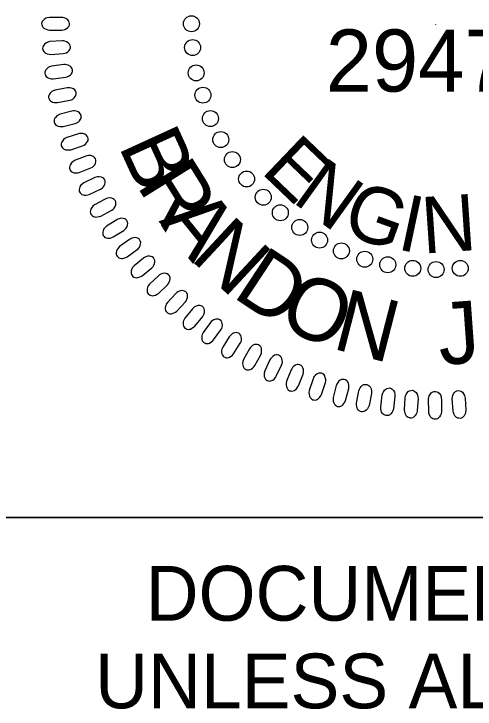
# Model space of a CAD drawing. Extents: x 505602 to 507286, y 483109 to 484209.
# Drawn here: x 507076.9 to 507123.2, y 484026.9 to 484096.7 of the extents above; entities that cross this region are included whole.
import ezdxf

# ---------------------------------------------------------------- set-up
doc = ezdxf.new("R2010")
doc.units = 0
for name, color, linetype in [('Sheet PE Seal Cell', 7, 'Continuous'), ('Sheet Profile CELL', 7, 'Continuous'), ('Sheet Sticker Exception Certification CELL', 7, 'Continuous')]:
    doc.layers.add(name, color=color, linetype=linetype)

msp = doc.modelspace()

# ---------------------------------------------------------------- linework, layer by layer
at = {"layer": 'Sheet PE Seal Cell'}
msp.add_line((507119.206, 484095.727), (507119.206, 484095.68), dxfattribs=at)
for points in [[(507081.659, 484096.389), (507080.432, 484096.39), (507080.213, 484096.352), (507080.073, 484096.3), (507079.904, 484096.188), (507079.794, 484096.091), (507079.714, 484095.978), (507079.674, 484095.874), (507079.654, 484095.762), (507079.674, 484095.65), (507079.704, 484095.53), (507079.763, 484095.426), (507079.864, 484095.321), (507079.943, 484095.261), (507080.093, 484095.194), (507080.273, 484095.134), (507080.432, 484095.111), (507081.689, 484095.103), (507081.858, 484095.126), (507081.998, 484095.171), (507082.157, 484095.261), (507082.297, 484095.372), (507082.377, 484095.47), (507082.437, 484095.626), (507082.457, 484095.776), (507082.416, 484095.926), (507082.367, 484096.03), (507082.268, 484096.158), (507082.098, 484096.277), (507081.918, 484096.344), (507081.789, 484096.374)], [(507081.712, 484094.032), (507080.487, 484093.955), (507080.271, 484093.904), (507080.134, 484093.844), (507079.972, 484093.721), (507079.868, 484093.617), (507079.796, 484093.5), (507079.763, 484093.393), (507079.75, 484093.279), (507079.777, 484093.17), (507079.815, 484093.051), (507079.88, 484092.951), (507079.987, 484092.853), (507080.07, 484092.798), (507080.223, 484092.74), (507080.406, 484092.692), (507080.566, 484092.679), (507081.822, 484092.75), (507081.99, 484092.784), (507082.126, 484092.837), (507082.279, 484092.937), (507082.412, 484093.057), (507082.486, 484093.159), (507082.536, 484093.319), (507082.546, 484093.47), (507082.497, 484093.617), (507082.44, 484093.718), (507082.333, 484093.839), (507082.157, 484093.947), (507081.973, 484094.003), (507081.842, 484094.025)], [(507081.876, 484091.651), (507080.659, 484091.497), (507080.446, 484091.432), (507080.314, 484091.364), (507080.16, 484091.231), (507080.063, 484091.121), (507079.998, 484090.999), (507079.972, 484090.891), (507079.966, 484090.777), (507080, 484090.668), (507080.044, 484090.553), (507080.116, 484090.457), (507080.229, 484090.366), (507080.316, 484090.316), (507080.472, 484090.268), (507080.658, 484090.231), (507080.819, 484090.229), (507082.067, 484090.378), (507082.232, 484090.422), (507082.365, 484090.484), (507082.512, 484090.593), (507082.636, 484090.721), (507082.704, 484090.828), (507082.743, 484090.991), (507082.744, 484091.142), (507082.686, 484091.285), (507082.623, 484091.383), (507082.509, 484091.497), (507082.326, 484091.594), (507082.139, 484091.638), (507082.007, 484091.652)], [(507082.21, 484089.325), (507081.004, 484089.096), (507080.796, 484089.018), (507080.669, 484088.941), (507080.523, 484088.798), (507080.433, 484088.683), (507080.376, 484088.557), (507080.356, 484088.447), (507080.358, 484088.333), (507080.398, 484088.227), (507080.45, 484088.115), (507080.528, 484088.023), (507080.646, 484087.94), (507080.735, 484087.896), (507080.895, 484087.857), (507081.083, 484087.832), (507081.243, 484087.84), (507082.479, 484088.068), (507082.642, 484088.122), (507082.771, 484088.192), (507082.91, 484088.31), (507083.027, 484088.446), (507083.087, 484088.556), (507083.116, 484088.721), (507083.108, 484088.873), (507083.041, 484089.012), (507082.972, 484089.105), (507082.85, 484089.211), (507082.662, 484089.297), (507082.472, 484089.33), (507082.34, 484089.334)], [(507082.689, 484086.984), (507081.501, 484086.679), (507081.298, 484086.588), (507081.175, 484086.504), (507081.039, 484086.353), (507080.957, 484086.231), (507080.907, 484086.103), (507080.895, 484085.991), (507080.903, 484085.878), (507080.95, 484085.775), (507081.009, 484085.666), (507081.093, 484085.579), (507081.216, 484085.503), (507081.308, 484085.464), (507081.469, 484085.436), (507081.658, 484085.423), (507081.818, 484085.441), (507083.037, 484085.746), (507083.196, 484085.81), (507083.32, 484085.888), (507083.452, 484086.015), (507083.56, 484086.158), (507083.613, 484086.271), (507083.632, 484086.439), (507083.614, 484086.589), (507083.538, 484086.723), (507083.464, 484086.812), (507083.336, 484086.911), (507083.142, 484086.984), (507082.951, 484087.005), (507082.818, 484087.001)], [(507083.343, 484084.7), (507082.176, 484084.321), (507081.979, 484084.218), (507081.862, 484084.126), (507081.735, 484083.966), (507081.661, 484083.84), (507081.62, 484083.709), (507081.615, 484083.597), (507081.63, 484083.484), (507081.684, 484083.384), (507081.749, 484083.279), (507081.838, 484083.198), (507081.966, 484083.13), (507082.059, 484083.097), (507082.223, 484083.079), (507082.412, 484083.078), (507082.571, 484083.106), (507083.768, 484083.486), (507083.922, 484083.56), (507084.042, 484083.646), (507084.165, 484083.781), (507084.263, 484083.93), (507084.31, 484084.047), (507084.318, 484084.215), (507084.291, 484084.364), (507084.207, 484084.493), (507084.127, 484084.578), (507083.993, 484084.668), (507083.795, 484084.729), (507083.603, 484084.738), (507083.471, 484084.726)], [(507084.102, 484082.463), (507082.961, 484082.012), (507082.77, 484081.896), (507082.659, 484081.796), (507082.543, 484081.63), (507082.477, 484081.499), (507082.444, 484081.365), (507082.446, 484081.254), (507082.468, 484081.142), (507082.528, 484081.045), (507082.6, 484080.945), (507082.693, 484080.869), (507082.825, 484080.809), (507082.921, 484080.783), (507083.086, 484080.775), (507083.274, 484080.786), (507083.431, 484080.823), (507084.602, 484081.278), (507084.752, 484081.362), (507084.865, 484081.455), (507084.98, 484081.597), (507085.069, 484081.752), (507085.108, 484081.872), (507085.105, 484082.04), (507085.069, 484082.187), (507084.977, 484082.31), (507084.892, 484082.39), (507084.753, 484082.472), (507084.551, 484082.519), (507084.359, 484082.517), (507084.228, 484082.496)], [(507085.001, 484080.304), (507083.891, 484079.782), (507083.709, 484079.654), (507083.604, 484079.548), (507083.499, 484079.374), (507083.441, 484079.239), (507083.416, 484079.104), (507083.425, 484078.992), (507083.454, 484078.882), (507083.52, 484078.79), (507083.598, 484078.694), (507083.697, 484078.624), (507083.832, 484078.573), (507083.929, 484078.552), (507084.093, 484078.555), (507084.281, 484078.578), (507084.435, 484078.625), (507085.576, 484079.152), (507085.719, 484079.245), (507085.827, 484079.345), (507085.932, 484079.494), (507086.012, 484079.655), (507086.043, 484079.777), (507086.03, 484079.945), (507085.984, 484080.089), (507085.884, 484080.206), (507085.794, 484080.28), (507085.651, 484080.353), (507085.446, 484080.388), (507085.255, 484080.373), (507085.125, 484080.345)], [(507086.049, 484078.155), (507084.973, 484077.564), (507084.799, 484077.426), (507084.702, 484077.313), (507084.607, 484077.133), (507084.558, 484076.994), (507084.542, 484076.858), (507084.557, 484076.747), (507084.594, 484076.639), (507084.666, 484076.551), (507084.75, 484076.461), (507084.852, 484076.397), (507084.99, 484076.354), (507085.089, 484076.34), (507085.252, 484076.353), (507085.438, 484076.387), (507085.589, 484076.443), (507086.694, 484077.042), (507086.832, 484077.144), (507086.932, 484077.251), (507087.029, 484077.406), (507087.097, 484077.571), (507087.121, 484077.695), (507087.097, 484077.861), (507087.043, 484078.002), (507086.936, 484078.114), (507086.842, 484078.181), (507086.693, 484078.245), (507086.487, 484078.268), (507086.297, 484078.24), (507086.169, 484078.204)], [(507087.205, 484076.08), (507086.169, 484075.423), (507086.003, 484075.274), (507085.914, 484075.155), (507085.83, 484074.969), (507085.79, 484074.829), (507085.783, 484074.691), (507085.805, 484074.582), (507085.848, 484074.476), (507085.926, 484074.393), (507086.015, 484074.307), (507086.121, 484074.251), (507086.261, 484074.216), (507086.36, 484074.208), (507086.523, 484074.232), (507086.707, 484074.278), (507086.853, 484074.343), (507087.919, 484075.01), (507088.05, 484075.12), (507088.144, 484075.234), (507088.23, 484075.394), (507088.288, 484075.563), (507088.304, 484075.688), (507088.27, 484075.853), (507088.207, 484075.99), (507088.093, 484076.095), (507087.995, 484076.156), (507087.842, 484076.21), (507087.635, 484076.22), (507087.447, 484076.181), (507087.322, 484076.137)], [(507088.482, 484074.105), (507087.488, 484073.384), (507087.333, 484073.225), (507087.25, 484073.101), (507087.179, 484072.91), (507087.148, 484072.767), (507087.149, 484072.63), (507087.178, 484072.522), (507087.228, 484072.419), (507087.31, 484072.34), (507087.405, 484072.261), (507087.515, 484072.211), (507087.657, 484072.186), (507087.756, 484072.184), (507087.917, 484072.217), (507088.097, 484072.274), (507088.24, 484072.35), (507089.261, 484073.082), (507089.385, 484073.2), (507089.471, 484073.319), (507089.548, 484073.485), (507089.595, 484073.657), (507089.603, 484073.783), (507089.559, 484073.945), (507089.487, 484074.078), (507089.367, 484074.175), (507089.265, 484074.231), (507089.11, 484074.275), (507088.903, 484074.272), (507088.717, 484074.221), (507088.595, 484074.169)], [(507089.885, 484072.224), (507088.939, 484071.442), (507088.794, 484071.274), (507088.72, 484071.144), (507088.661, 484070.95), (507088.638, 484070.805), (507088.648, 484070.668), (507088.684, 484070.562), (507088.74, 484070.463), (507088.827, 484070.389), (507088.926, 484070.316), (507089.039, 484070.273), (507089.182, 484070.257), (507089.282, 484070.261), (507089.44, 484070.305), (507089.616, 484070.373), (507089.754, 484070.457), (507090.727, 484071.252), (507090.844, 484071.377), (507090.922, 484071.501), (507090.988, 484071.672), (507091.025, 484071.847), (507091.024, 484071.973), (507090.97, 484072.132), (507090.89, 484072.26), (507090.764, 484072.349), (507090.659, 484072.398), (507090.501, 484072.433), (507090.295, 484072.417), (507090.113, 484072.355), (507089.994, 484072.295)], [(507091.395, 484070.453), (507090.5, 484069.614), (507090.366, 484069.437), (507090.3, 484069.303), (507090.253, 484069.105), (507090.24, 484068.959), (507090.258, 484068.823), (507090.301, 484068.719), (507090.363, 484068.624), (507090.454, 484068.556), (507090.558, 484068.489), (507090.673, 484068.453), (507090.818, 484068.446), (507090.916, 484068.456), (507091.072, 484068.51), (507091.244, 484068.589), (507091.375, 484068.681), (507092.296, 484069.536), (507092.405, 484069.669), (507092.476, 484069.797), (507092.531, 484069.971), (507092.556, 484070.148), (507092.548, 484070.274), (507092.484, 484070.43), (507092.396, 484070.552), (507092.265, 484070.634), (507092.157, 484070.676), (507091.997, 484070.701), (507091.792, 484070.672), (507091.614, 484070.598), (507091.5, 484070.531)], [(507093.131, 484068.675), (507092.29, 484067.781), (507092.167, 484067.596), (507092.11, 484067.458), (507092.075, 484067.258), (507092.071, 484067.11), (507092.098, 484066.976), (507092.147, 484066.876), (507092.215, 484066.784), (507092.31, 484066.722), (507092.419, 484066.662), (507092.535, 484066.633), (507092.68, 484066.635), (507092.778, 484066.652), (507092.93, 484066.715), (507093.096, 484066.805), (507093.222, 484066.905), (507094.088, 484067.817), (507094.187, 484067.955), (507094.25, 484068.088), (507094.294, 484068.265), (507094.308, 484068.444), (507094.292, 484068.568), (507094.219, 484068.72), (507094.123, 484068.837), (507093.987, 484068.91), (507093.876, 484068.945), (507093.716, 484068.96), (507093.513, 484068.918), (507093.34, 484068.833), (507093.23, 484068.759)], [(507094.821, 484067.145), (507094.038, 484066.2), (507093.927, 484066.007), (507093.878, 484065.866), (507093.856, 484065.664), (507093.862, 484065.517), (507093.897, 484065.384), (507093.952, 484065.286), (507094.026, 484065.199), (507094.124, 484065.144), (507094.236, 484065.091), (507094.354, 484065.07), (507094.499, 484065.081), (507094.596, 484065.103), (507094.743, 484065.176), (507094.903, 484065.276), (507095.023, 484065.384), (507095.83, 484066.348), (507095.921, 484066.493), (507095.974, 484066.63), (507096.008, 484066.809), (507096.011, 484066.988), (507095.986, 484067.112), (507095.903, 484067.258), (507095.801, 484067.368), (507095.661, 484067.433), (507095.547, 484067.461), (507095.386, 484067.465), (507095.187, 484067.411), (507095.019, 484067.316), (507094.914, 484067.235)], [(507096.601, 484065.744), (507095.88, 484064.752), (507095.781, 484064.553), (507095.741, 484064.409), (507095.732, 484064.205), (507095.747, 484064.059), (507095.79, 484063.929), (507095.851, 484063.835), (507095.93, 484063.753), (507096.033, 484063.703), (507096.148, 484063.658), (507096.267, 484063.644), (507096.41, 484063.664), (507096.506, 484063.692), (507096.648, 484063.775), (507096.802, 484063.884), (507096.914, 484064), (507097.659, 484065.012), (507097.74, 484065.162), (507097.786, 484065.302), (507097.808, 484065.483), (507097.8, 484065.662), (507097.767, 484065.784), (507097.676, 484065.925), (507097.566, 484066.029), (507097.422, 484066.085), (507097.308, 484066.105), (507097.147, 484066.1), (507096.95, 484066.033), (507096.79, 484065.927), (507096.69, 484065.84)], [(507098.503, 484064.331), (507097.846, 484063.295), (507097.759, 484063.09), (507097.728, 484062.944), (507097.732, 484062.741), (507097.756, 484062.597), (507097.808, 484062.469), (507097.874, 484062.379), (507097.959, 484062.302), (507098.063, 484062.259), (507098.181, 484062.22), (507098.301, 484062.214), (507098.443, 484062.242), (507098.536, 484062.278), (507098.673, 484062.368), (507098.82, 484062.487), (507098.924, 484062.61), (507099.604, 484063.667), (507099.676, 484063.822), (507099.713, 484063.964), (507099.723, 484064.147), (507099.703, 484064.325), (507099.663, 484064.444), (507099.564, 484064.579), (507099.448, 484064.676), (507099.3, 484064.722), (507099.185, 484064.736), (507099.025, 484064.721), (507098.833, 484064.642), (507098.679, 484064.526), (507098.585, 484064.433)], [(507100.521, 484063.115), (507099.93, 484062.041), (507099.857, 484061.831), (507099.835, 484061.683), (507099.852, 484061.48), (507099.884, 484061.337), (507099.944, 484061.213), (507100.016, 484061.128), (507100.105, 484061.056), (507100.212, 484061.02), (507100.332, 484060.988), (507100.452, 484060.99), (507100.592, 484061.028), (507100.683, 484061.068), (507100.814, 484061.167), (507100.953, 484061.296), (507101.05, 484061.424), (507101.662, 484062.522), (507101.723, 484062.681), (507101.751, 484062.826), (507101.75, 484063.008), (507101.72, 484063.185), (507101.673, 484063.301), (507101.564, 484063.43), (507101.442, 484063.519), (507101.292, 484063.556), (507101.176, 484063.563), (507101.017, 484063.537), (507100.831, 484063.446), (507100.685, 484063.321), (507100.596, 484063.222)], [(507102.58, 484062.009), (507102.058, 484060.899), (507101.998, 484060.685), (507101.986, 484060.536), (507102.015, 484060.335), (507102.056, 484060.194), (507102.124, 484060.075), (507102.201, 484059.994), (507102.295, 484059.928), (507102.404, 484059.899), (507102.525, 484059.874), (507102.645, 484059.884), (507102.783, 484059.93), (507102.871, 484059.976), (507102.995, 484060.083), (507103.126, 484060.22), (507103.215, 484060.354), (507103.757, 484061.488), (507103.808, 484061.652), (507103.827, 484061.797), (507103.814, 484061.979), (507103.773, 484062.153), (507103.718, 484062.267), (507103.602, 484062.388), (507103.474, 484062.47), (507103.323, 484062.497), (507103.206, 484062.497), (507103.049, 484062.461), (507102.869, 484062.359), (507102.732, 484062.224), (507102.65, 484062.12)], [(507104.708, 484061.001), (507104.256, 484059.86), (507104.21, 484059.642), (507104.207, 484059.494), (507104.249, 484059.294), (507104.298, 484059.157), (507104.374, 484059.041), (507104.456, 484058.966), (507104.553, 484058.905), (507104.664, 484058.883), (507104.787, 484058.867), (507104.906, 484058.883), (507105.04, 484058.938), (507105.125, 484058.99), (507105.243, 484059.104), (507105.364, 484059.249), (507105.444, 484059.389), (507105.914, 484060.555), (507105.956, 484060.72), (507105.965, 484060.867), (507105.941, 484061.048), (507105.888, 484061.219), (507105.827, 484061.33), (507105.703, 484061.443), (507105.571, 484061.517), (507105.418, 484061.534), (507105.302, 484061.526), (507105.147, 484061.481), (507104.974, 484061.367), (507104.845, 484061.225), (507104.77, 484061.116)], [(507106.917, 484060.099), (507106.537, 484058.932), (507106.505, 484058.712), (507106.511, 484058.563), (507106.565, 484058.367), (507106.624, 484058.232), (507106.706, 484058.122), (507106.793, 484058.052), (507106.894, 484057.998), (507107.006, 484057.983), (507107.13, 484057.974), (507107.247, 484057.998), (507107.378, 484058.061), (507107.459, 484058.118), (507107.57, 484058.24), (507107.682, 484058.392), (507107.753, 484058.537), (507108.149, 484059.729), (507108.18, 484059.898), (507108.18, 484060.044), (507108.144, 484060.223), (507108.081, 484060.391), (507108.013, 484060.497), (507107.882, 484060.603), (507107.746, 484060.668), (507107.592, 484060.676), (507107.477, 484060.66), (507107.325, 484060.606), (507107.159, 484060.481), (507107.039, 484060.331), (507106.971, 484060.217)], [(507109.25, 484059.426), (507108.944, 484058.237), (507108.926, 484058.017), (507108.941, 484057.868), (507109.008, 484057.675), (507109.074, 484057.545), (507109.164, 484057.44), (507109.255, 484057.375), (507109.358, 484057.328), (507109.472, 484057.32), (507109.595, 484057.319), (507109.711, 484057.35), (507109.837, 484057.421), (507109.915, 484057.483), (507110.018, 484057.612), (507110.12, 484057.771), (507110.182, 484057.92), (507110.502, 484059.134), (507110.522, 484059.304), (507110.513, 484059.451), (507110.466, 484059.628), (507110.393, 484059.791), (507110.318, 484059.892), (507110.181, 484059.989), (507110.042, 484060.046), (507109.886, 484060.044), (507109.773, 484060.022), (507109.625, 484059.957), (507109.467, 484059.823), (507109.357, 484059.665), (507109.296, 484059.548)], [(507112.772, 484058.638), (507112.541, 484057.433), (507112.463, 484057.225), (507112.386, 484057.097), (507112.244, 484056.951), (507112.128, 484056.862), (507112.003, 484056.805), (507111.892, 484056.785), (507111.778, 484056.787), (507111.673, 484056.828), (507111.56, 484056.879), (507111.469, 484056.958), (507111.385, 484057.075), (507111.341, 484057.165), (507111.303, 484057.324), (507111.278, 484057.512), (507111.286, 484057.673), (507111.514, 484058.908), (507111.568, 484059.071), (507111.639, 484059.2), (507111.757, 484059.34), (507111.893, 484059.456), (507112.003, 484059.516), (507112.168, 484059.545), (507112.32, 484059.536), (507112.458, 484059.469), (507112.552, 484059.4), (507112.658, 484059.28), (507112.743, 484059.09), (507112.776, 484058.901), (507112.781, 484058.769)], [(507115.138, 484058.312), (507114.983, 484057.095), (507114.919, 484056.882), (507114.849, 484056.75), (507114.717, 484056.595), (507114.607, 484056.499), (507114.485, 484056.434), (507114.377, 484056.408), (507114.263, 484056.402), (507114.155, 484056.436), (507114.039, 484056.481), (507113.943, 484056.553), (507113.852, 484056.666), (507113.802, 484056.752), (507113.754, 484056.909), (507113.718, 484057.094), (507113.715, 484057.255), (507113.866, 484058.503), (507113.909, 484058.668), (507113.972, 484058.801), (507114.08, 484058.948), (507114.209, 484059.073), (507114.316, 484059.139), (507114.479, 484059.179), (507114.63, 484059.18), (507114.773, 484059.122), (507114.871, 484059.059), (507114.985, 484058.945), (507115.081, 484058.761), (507115.126, 484058.574), (507115.139, 484058.442)], [(507117.455, 484058.115), (507117.377, 484056.89), (507117.326, 484056.674), (507117.265, 484056.537), (507117.143, 484056.375), (507117.039, 484056.271), (507116.922, 484056.2), (507116.815, 484056.166), (507116.701, 484056.154), (507116.591, 484056.181), (507116.474, 484056.218), (507116.373, 484056.284), (507116.275, 484056.39), (507116.22, 484056.474), (507116.162, 484056.627), (507116.114, 484056.81), (507116.102, 484056.971), (507116.173, 484058.225), (507116.207, 484058.393), (507116.261, 484058.53), (507116.36, 484058.683), (507116.48, 484058.816), (507116.583, 484058.889), (507116.743, 484058.939), (507116.894, 484058.949), (507117.041, 484058.9), (507117.141, 484058.843), (507117.262, 484058.736), (507117.37, 484058.559), (507117.427, 484058.375), (507117.448, 484058.245)], [(507119.808, 484058.043), (507119.808, 484056.816), (507119.77, 484056.597), (507119.718, 484056.457), (507119.606, 484056.287), (507119.508, 484056.177), (507119.396, 484056.098), (507119.292, 484056.058), (507119.18, 484056.038), (507119.068, 484056.058), (507118.948, 484056.088), (507118.843, 484056.147), (507118.738, 484056.248), (507118.679, 484056.328), (507118.611, 484056.477), (507118.552, 484056.657), (507118.529, 484056.816), (507118.522, 484058.073), (507118.545, 484058.242), (507118.59, 484058.382), (507118.679, 484058.542), (507118.791, 484058.681), (507118.889, 484058.761), (507119.046, 484058.821), (507119.196, 484058.84), (507119.345, 484058.801), (507119.45, 484058.751), (507119.577, 484058.651), (507119.696, 484058.482), (507119.764, 484058.301), (507119.793, 484058.172)], [(507122.175, 484058.165), (507122.251, 484056.94), (507122.228, 484056.719), (507122.185, 484056.577), (507122.083, 484056.4), (507121.994, 484056.285), (507121.886, 484056.198), (507121.785, 484056.152), (507121.674, 484056.125), (507121.561, 484056.139), (507121.44, 484056.161), (507121.331, 484056.214), (507121.22, 484056.307), (507121.156, 484056.383), (507121.08, 484056.528), (507121.009, 484056.703), (507120.976, 484056.861), (507120.89, 484058.115), (507120.902, 484058.285), (507120.938, 484058.427), (507121.018, 484058.592), (507121.121, 484058.739), (507121.213, 484058.824), (507121.366, 484058.894), (507121.514, 484058.923), (507121.665, 484058.892), (507121.773, 484058.849), (507121.906, 484058.758), (507122.036, 484058.596), (507122.115, 484058.421), (507122.153, 484058.294)]]:
    msp.add_lwpolyline(points, close=True, dxfattribs=at)
for centre in [(507094.698, 484095.754), (507094.817, 484093.363), (507095.174, 484090.814), (507095.85, 484088.582), (507096.606, 484086.232), (507097.641, 484084.12), (507098.81, 484082.116), (507100.242, 484080.164), (507101.914, 484078.331), (507103.625, 484076.777), (507105.576, 484075.302), (507107.566, 484074.026), (507109.755, 484072.95), (507112.104, 484072.113), (507114.413, 484071.554), (507116.921, 484071.195), (507119.27, 484071.075), (507121.699, 484071.193)]:
    msp.add_circle(centre, 0.801, dxfattribs=at)
at = {"layer": 'Sheet Profile CELL'}
msp.add_lwpolyline([(507069.03, 484158.662), (507169.08, 484158.662), (507169.08, 484046.162), (507069.03, 484046.162)], close=True, dxfattribs=at)
at = {"layer": 'Sheet Sticker Exception Certification CELL'}
msp.add_line((507069.03, 484046.162), (507269.067, 484046.162), dxfattribs=at)
msp.add_line((507069.03, 484046.162), (507269.067, 484046.162), dxfattribs=at)

# ---------------------------------------------------------------- texts
at = {"layer": 'Sheet PE Seal Cell'}
for s, height, rotation, p in [('29470', 6.2363, 359.98136, (507108.193, 484088.941)), ('B', 6.236, 294.5897, (507087.323, 484083.503)), ('E', 5.669, 316.26559, (507101.563, 484080.882)), ('R', 6.236, 301.86473, (507089.134, 484079.547)), ('N', 5.669, 324.20538, (507104.698, 484077.927)), ('G', 5.669, 340.08498, (507109.592, 484074.828)), ('I', 5.669, 348.02477, (507115.221, 484073.139)), ('N', 5.669, 3.90437, (507117.974, 484072.666)), ('A', 6.236, 308.98157, (507091.377, 484075.928)), ('N', 6.236, 317.09274, (507094.456, 484072.18)), ('D', 6.236, 326.58243, (507098.686, 484068.399)), ('O', 6.236, 335.45066, (507103.152, 484065.541)), ('N', 6.236, 345.5505, (507108.704, 484063.17)), ('J', 6.236, 4.1457, (507119.655, 484061.477))]:
    msp.add_text(s, height=height, rotation=rotation, dxfattribs=at).set_placement(p)
at = {"layer": 'Sheet Sticker Exception Certification CELL'}
for s, p in [('DOCUMENT NOT CONSIDERED FINAL', (507090.101, 484035.816)), ('DOCUMENT NOT CONSIDERED FINAL', (507090.101, 484035.816)), ('UNLESS ALL SIGNATURES COMPLETED', (507085.03, 484027.016)), ('UNLESS ALL SIGNATURES COMPLETED', (507085.03, 484027.016))]:
    msp.add_text(s, height=5.5, dxfattribs=at).set_placement(p)

doc.saveas('drawing.dxf')
